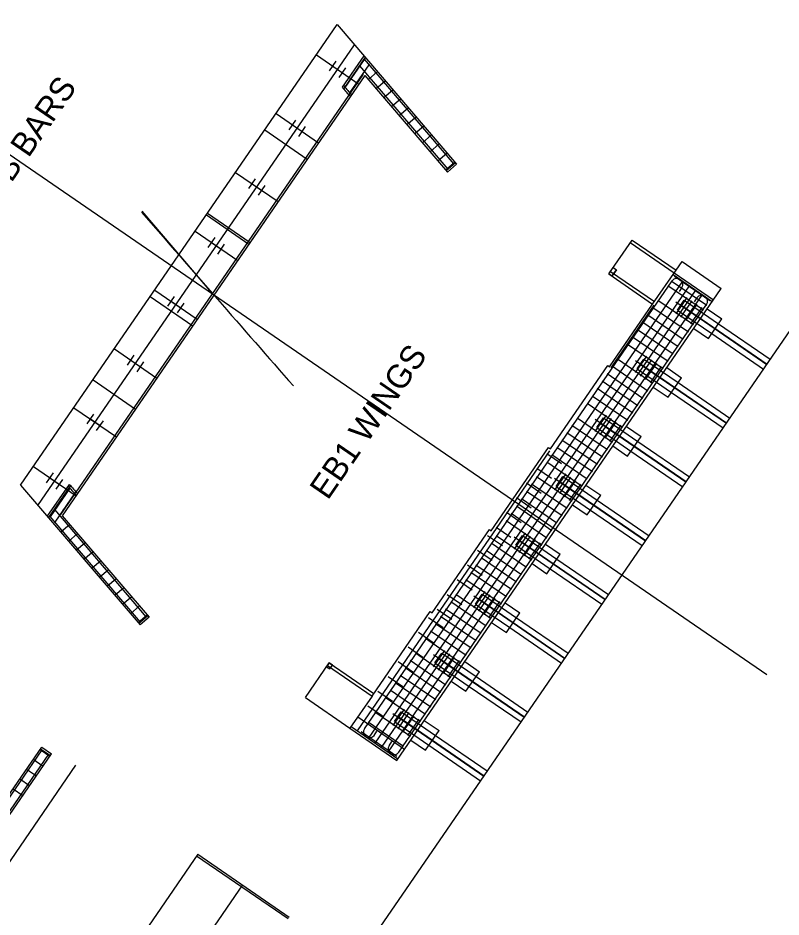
# Model space of a CAD drawing. Extents: x 2378999 to 2381348, y 331302 to 333122.
# Drawn here: x 2379189.4 to 2379253.5, y 331373.2 to 331448.8 of the extents above; entities that cross this region are included whole.
import ezdxf

# ---------------------------------------------------------------- set-up
doc = ezdxf.new("R2010")
doc.units = 0
for name, color, linetype in [('Arrowhead Terminators', 7, 'Continuous'), ('Dimension Lines', 7, 'Continuous'), ('Dimension Lines CELL', 7, 'Continuous'), ('Mis Work Point CELL', 7, 'Continuous'), ('P_SMU_Girder_Concrete', 7, 'Continuous'), ('P_SMU_Mis_Long_Chord', 7, 'Continuous'), ('P_SMU_Rebar_B_Bar', 7, 'Continuous'), ('P_SMU_Rebar_H_Bar', 7, 'Continuous'), ('P_SMU_Rebar_K_Bar', 7, 'Continuous'), ('P_SMU_Rebar_U_Bar', 7, 'Continuous'), ('P_SMU_Rebar_V_Bar', 7, 'Continuous'), ('Plan Sheet CELL', 7, 'Continuous'), ('Rebar Lines', 7, 'Continuous'), ('Scratch_Level_0', 7, 'Continuous'), ('Sup Concrete Slab Lines', 7, 'Continuous'), ('Text', 7, 'Continuous')]:
    doc.layers.add(name, color=color, linetype=linetype)

msp = doc.modelspace()

# ---------------------------------------------------------------- linework, layer by layer
at = {"layer": 'Arrowhead Terminators'}
for p, q in [((2379218.53, 331388.983), (2379244.401, 331426.64)), ((2379218.871, 331388.155), (2379245.297, 331426.619)), ((2379219.42, 331387.778), (2379245.846, 331426.241)), ((2379219.97, 331387.4), (2379246.396, 331425.864)), ((2379245.208, 331426.085), (2379244.972, 331425.742)), ((2379220.519, 331387.023), (2379246.945, 331425.486)), ((2379246.479, 331425.212), (2379246.243, 331424.869)), ((2379221.414, 331387.002), (2379247.286, 331424.658)), ((2379217.932, 331388.8), (2379234.115, 331412.355)), ((2379219.337, 331388.429), (2379219.573, 331388.772)), ((2379220.607, 331387.556), (2379220.843, 331387.899))]:
    msp.add_line(p, q, dxfattribs=at)
for centre, start, end in [((2379244.805, 331426.363), 325.50932, 145.50932), ((2379246.883, 331424.935), 325.50932, 145.50932), ((2379218.933, 331388.706), 145.50932, 325.50932), ((2379221.011, 331387.279), 145.50932, 325.50932)]:
    msp.add_arc(centre, 0.49, start, end, dxfattribs=at)
at = {"layer": 'Dimension Lines'}
for p, q in [((2379244.312, 331426.658), (2379247.3, 331424.605)), ((2379244.583, 331427.052), (2379247.571, 331424.999)), ((2379244.042, 331426.264), (2379247.03, 331424.211)), ((2379243.193, 331425.028), (2379246.18, 331422.975)), ((2379244.725, 331423.874), (2379245.669, 331425.247)), ((2379245.137, 331423.591), (2379246.081, 331424.964)), ((2379242.768, 331424.41), (2379245.756, 331422.357)), ((2379245.549, 331423.308), (2379246.493, 331424.681)), ((2379245.961, 331423.024), (2379246.905, 331424.398)), ((2379242.343, 331423.791), (2379245.331, 331421.739)), ((2379241.918, 331423.173), (2379244.906, 331421.121)), ((2379241.069, 331421.937), (2379244.057, 331419.884)), ((2379241.494, 331422.555), (2379244.482, 331420.502)), ((2379240.644, 331421.319), (2379243.632, 331419.266)), ((2379239.795, 331420.083), (2379242.783, 331418.03)), ((2379241.328, 331418.928), (2379242.271, 331420.302)), ((2379241.74, 331418.645), (2379242.683, 331420.019)), ((2379242.152, 331418.362), (2379243.096, 331419.736)), ((2379239.37, 331419.464), (2379242.358, 331417.412)), ((2379242.564, 331418.079), (2379243.508, 331419.453)), ((2379238.521, 331418.228), (2379241.509, 331416.175)), ((2379238.946, 331418.846), (2379241.933, 331416.793)), ((2379238.096, 331417.61), (2379241.084, 331415.557)), ((2379237.671, 331416.992), (2379240.659, 331414.939)), ((2379237.247, 331416.374), (2379240.235, 331414.321)), ((2379236.397, 331415.137), (2379239.385, 331413.084)), ((2379237.93, 331413.983), (2379238.874, 331415.357)), ((2379235.973, 331414.519), (2379238.96, 331412.466)), ((2379238.342, 331413.7), (2379239.286, 331415.074)), ((2379238.754, 331413.417), (2379239.698, 331414.791)), ((2379239.166, 331413.134), (2379240.11, 331414.507)), ((2379235.548, 331413.901), (2379238.536, 331411.848)), ((2379235.123, 331413.283), (2379238.111, 331411.23)), ((2379234.699, 331412.665), (2379237.686, 331410.612)), ((2379233.849, 331411.428), (2379236.837, 331409.375)), ((2379234.274, 331412.046), (2379237.262, 331409.994)), ((2379233, 331410.192), (2379235.987, 331408.139)), ((2379234.532, 331409.038), (2379235.476, 331410.412)), ((2379234.944, 331408.755), (2379235.888, 331410.128)), ((2379235.356, 331408.472), (2379236.3, 331409.845)), ((2379232.575, 331409.574), (2379235.563, 331407.521)), ((2379235.769, 331408.188), (2379236.712, 331409.562)), ((2379231.726, 331408.337), (2379234.713, 331406.285)), ((2379232.15, 331408.956), (2379235.138, 331406.903)), ((2379231.301, 331407.719), (2379234.289, 331405.667)), ((2379230.876, 331407.101), (2379233.864, 331405.048)), ((2379230.451, 331406.483), (2379233.439, 331404.43)), ((2379231.135, 331404.093), (2379232.078, 331405.466)), ((2379229.177, 331404.628), (2379232.165, 331402.576)), ((2379229.602, 331405.247), (2379232.59, 331403.194)), ((2379231.547, 331403.809), (2379232.491, 331405.183)), ((2379231.959, 331403.526), (2379232.903, 331404.9)), ((2379232.371, 331403.243), (2379233.315, 331404.617)), ((2379228.753, 331404.01), (2379231.74, 331401.958)), ((2379228.328, 331403.392), (2379231.316, 331401.339)), ((2379227.903, 331402.774), (2379230.891, 331400.721)), ((2379227.054, 331401.538), (2379230.042, 331399.485)), ((2379227.479, 331402.156), (2379230.466, 331400.103)), ((2379226.204, 331400.301), (2379229.192, 331398.249)), ((2379227.737, 331399.147), (2379228.681, 331400.521)), ((2379228.149, 331398.864), (2379229.093, 331400.238)), ((2379225.78, 331399.683), (2379228.768, 331397.63)), ((2379228.561, 331398.581), (2379229.505, 331399.955)), ((2379228.973, 331398.298), (2379229.917, 331399.672)), ((2379225.355, 331399.065), (2379228.343, 331397.012)), ((2379224.506, 331397.829), (2379227.493, 331395.776)), ((2379224.93, 331398.447), (2379227.918, 331396.394)), ((2379224.081, 331397.21), (2379227.069, 331395.158)), ((2379223.656, 331396.592), (2379226.644, 331394.54)), ((2379224.339, 331394.202), (2379225.283, 331395.576)), ((2379222.382, 331394.738), (2379225.37, 331392.685)), ((2379222.807, 331395.356), (2379225.795, 331393.303)), ((2379224.751, 331393.919), (2379225.695, 331395.292)), ((2379225.164, 331393.636), (2379226.107, 331395.009)), ((2379225.576, 331393.353), (2379226.519, 331394.726)), ((2379221.957, 331394.12), (2379224.945, 331392.067)), ((2379221.533, 331393.501), (2379224.52, 331391.449)), ((2379221.108, 331392.883), (2379224.096, 331390.831)), ((2379220.683, 331392.265), (2379223.671, 331390.212)), ((2379220.259, 331391.647), (2379223.246, 331389.594)), ((2379219.409, 331390.411), (2379222.397, 331388.358)), ((2379220.942, 331389.257), (2379221.886, 331390.63)), ((2379221.354, 331388.973), (2379222.298, 331390.347)), ((2379218.835, 331389.575), (2379221.823, 331387.523)), ((2379221.766, 331388.69), (2379222.71, 331390.064)), ((2379222.178, 331388.407), (2379223.122, 331389.781)), ((2379218.261, 331388.74), (2379221.249, 331386.687))]:
    msp.add_line(p, q, dxfattribs=at)
at = {"layer": 'Dimension Lines CELL'}
msp.add_line((2379252.362, 331393.507), (2379066.398, 331521.272), dxfattribs=at)
at = {"layer": 'Mis Work Point CELL'}
for p, q in [((2379200.252, 331343.799), (2379277.28, 331455.914)), ((2379191.082, 331407.75), (2379217.696, 331446.488))]:
    msp.add_line(p, q, dxfattribs=at)
at = {"layer": 'P_SMU_Girder_Concrete'}
for p, q in [((2379215.592, 331444.294), (2379216.159, 331445.118)), ((2379215.875, 331444.706), (2379216.686, 331444.149)), ((2379216.403, 331443.737), (2379216.969, 331444.561)), ((2379212.195, 331439.348), (2379212.761, 331440.173)), ((2379212.478, 331439.76), (2379213.288, 331439.204)), ((2379213.005, 331438.792), (2379213.571, 331439.616)), ((2379208.797, 331434.403), (2379209.363, 331435.227)), ((2379209.08, 331434.815), (2379209.891, 331434.258)), ((2379209.608, 331433.846), (2379210.174, 331434.67)), ((2379205.399, 331429.458), (2379205.966, 331430.282)), ((2379205.683, 331429.87), (2379206.493, 331429.313)), ((2379206.21, 331428.901), (2379206.776, 331429.725)), ((2379202.002, 331424.512), (2379202.568, 331425.337)), ((2379244.845, 331424.196), (2379245.412, 331425.02)), ((2379245.412, 331425.02), (2379248.296, 331423.038)), ((2379202.285, 331424.925), (2379203.095, 331424.368)), ((2379202.812, 331423.956), (2379203.379, 331424.78)), ((2379245.118, 331424.593), (2379252.348, 331419.626)), ((2379245.139, 331424.623), (2379252.369, 331419.655)), ((2379244.845, 331424.196), (2379247.73, 331422.214)), ((2379248.296, 331423.038), (2379252.642, 331420.053)), ((2379247.73, 331422.214), (2379252.075, 331419.228)), ((2379198.604, 331419.567), (2379199.17, 331420.391)), ((2379198.887, 331419.979), (2379199.698, 331419.422)), ((2379199.415, 331419.01), (2379199.981, 331419.834)), ((2379241.448, 331419.25), (2379242.014, 331420.075)), ((2379241.741, 331419.677), (2379248.971, 331414.71)), ((2379242.014, 331420.075), (2379244.899, 331418.093)), ((2379241.448, 331419.25), (2379244.332, 331417.268)), ((2379241.72, 331419.648), (2379248.951, 331414.68)), ((2379244.899, 331418.093), (2379249.244, 331415.107)), ((2379244.332, 331417.268), (2379248.678, 331414.283)), ((2379195.207, 331414.622), (2379195.773, 331415.446)), ((2379238.05, 331414.305), (2379238.616, 331415.129)), ((2379238.616, 331415.129), (2379241.501, 331413.147)), ((2379195.49, 331415.034), (2379196.3, 331414.477)), ((2379196.017, 331414.065), (2379196.583, 331414.889)), ((2379238.323, 331414.702), (2379245.553, 331409.735)), ((2379238.343, 331414.732), (2379245.573, 331409.765)), ((2379238.05, 331414.305), (2379240.935, 331412.323)), ((2379241.501, 331413.147), (2379245.846, 331410.162)), ((2379240.935, 331412.323), (2379245.28, 331409.338)), ((2379191.809, 331409.676), (2379192.375, 331410.501)), ((2379192.092, 331410.089), (2379192.903, 331409.532)), ((2379192.619, 331409.12), (2379193.186, 331409.944)), ((2379234.652, 331409.36), (2379235.219, 331410.184)), ((2379235.219, 331410.184), (2379238.103, 331408.202)), ((2379234.652, 331409.36), (2379237.537, 331407.378)), ((2379234.925, 331409.757), (2379242.155, 331404.79)), ((2379234.946, 331409.787), (2379242.176, 331404.819)), ((2379238.103, 331408.202), (2379242.449, 331405.217)), ((2379237.537, 331407.378), (2379241.882, 331404.392)), ((2379231.255, 331404.414), (2379231.821, 331405.239)), ((2379231.528, 331404.812), (2379238.758, 331399.844)), ((2379231.548, 331404.842), (2379238.778, 331399.874)), ((2379231.821, 331405.239), (2379234.706, 331403.257)), ((2379231.255, 331404.414), (2379234.139, 331402.433)), ((2379234.706, 331403.257), (2379239.051, 331400.271)), ((2379234.139, 331402.433), (2379238.485, 331399.447)), ((2379227.857, 331399.469), (2379228.423, 331400.293)), ((2379228.423, 331400.293), (2379231.308, 331398.311)), ((2379227.857, 331399.469), (2379230.742, 331397.487)), ((2379228.13, 331399.866), (2379235.36, 331394.899)), ((2379228.15, 331399.896), (2379235.381, 331394.929)), ((2379231.308, 331398.311), (2379235.653, 331395.326)), ((2379230.742, 331397.487), (2379235.087, 331394.502)), ((2379224.459, 331394.524), (2379225.026, 331395.348)), ((2379224.732, 331394.921), (2379231.962, 331389.954)), ((2379224.753, 331394.951), (2379231.983, 331389.984)), ((2379225.026, 331395.348), (2379227.91, 331393.366)), ((2379224.459, 331394.524), (2379227.344, 331392.542)), ((2379227.91, 331393.366), (2379232.256, 331390.381)), ((2379227.344, 331392.542), (2379231.689, 331389.557)), ((2379221.062, 331389.579), (2379221.628, 331390.403)), ((2379221.628, 331390.403), (2379224.513, 331388.421)), ((2379221.062, 331389.579), (2379223.947, 331387.597)), ((2379221.335, 331389.976), (2379228.565, 331385.008)), ((2379221.355, 331390.006), (2379228.585, 331385.038)), ((2379224.513, 331388.421), (2379228.858, 331385.435)), ((2379223.947, 331387.597), (2379228.292, 331384.611))]:
    msp.add_line(p, q, dxfattribs=at)
at = {"layer": 'P_SMU_Mis_Long_Chord'}
msp.add_arc((2384538.133, 336083.063), 7080, 221.0615597, 221.2186539, dxfattribs=at)
at = {"layer": 'P_SMU_Rebar_B_Bar'}
for p, q in [((2379189.625, 331409.455), (2379216.239, 331448.193)), ((2379216.239, 331448.193), (2379226.276, 331436.446)), ((2379218.481, 331445.57), (2379216.665, 331442.926)), ((2379218.567, 331443.929), (2379193.125, 331406.897)), ((2379218.567, 331443.929), (2379225.516, 331435.796)), ((2379210.152, 331439.333), (2379213.724, 331436.879)), ((2379225.516, 331435.796), (2379226.276, 331436.446)), ((2379205.339, 331432.327), (2379208.91, 331429.873)), ((2379239.063, 331427.226), (2379241.024, 331430.081)), ((2379240.873, 331429.86), (2379244.567, 331427.322)), ((2379241.024, 331430.081), (2379244.719, 331427.543)), ((2379244.719, 331427.543), (2379245.224, 331428.279)), ((2379245.224, 331428.279), (2379248.521, 331426.014)), ((2379239.063, 331427.226), (2379242.757, 331424.688)), ((2379239.209, 331427.438), (2379242.903, 331424.9)), ((2379239.338, 331427.038), (2379239.703, 331427.569)), ((2379239.428, 331427.757), (2379239.703, 331427.569)), ((2379242.757, 331424.688), (2379244.719, 331427.543)), ((2379244.567, 331427.322), (2379247.864, 331425.057)), ((2379221.249, 331386.319), (2379248.521, 331426.014)), ((2379200.525, 331425.321), (2379204.097, 331422.867)), ((2379239.137, 331419.419), (2379242.757, 331424.688)), ((2379247.343, 331424.299), (2379248.579, 331423.45)), ((2379247.447, 331421.802), (2379248.579, 331423.45)), ((2379246.211, 331422.651), (2379247.447, 331421.802)), ((2379234.163, 331412.524), (2379238.976, 331419.529)), ((2379238.976, 331419.529), (2379239.137, 331419.419)), ((2379243.945, 331419.354), (2379245.182, 331418.505)), ((2379195.712, 331418.315), (2379199.284, 331415.862)), ((2379244.049, 331416.856), (2379245.182, 331418.505)), ((2379242.813, 331417.706), (2379244.049, 331416.856)), ((2379240.548, 331414.409), (2379241.784, 331413.559)), ((2379240.652, 331411.911), (2379241.784, 331413.559)), ((2379229.19, 331405.628), (2379234.003, 331412.633)), ((2379234.003, 331412.633), (2379234.163, 331412.524)), ((2379239.415, 331412.76), (2379240.652, 331411.911)), ((2379189.625, 331409.455), (2379199.661, 331397.708)), ((2379191.866, 331406.831), (2379193.72, 331409.529)), ((2379237.15, 331409.464), (2379238.387, 331408.614)), ((2379237.254, 331406.966), (2379238.387, 331408.614)), ((2379236.018, 331407.815), (2379237.254, 331406.966)), ((2379193.125, 331406.897), (2379200.421, 331398.357)), ((2379224.216, 331398.732), (2379229.029, 331405.738)), ((2379229.029, 331405.738), (2379229.19, 331405.628)), ((2379233.753, 331404.518), (2379234.989, 331403.669)), ((2379233.856, 331402.02), (2379234.989, 331403.669)), ((2379232.62, 331402.87), (2379233.856, 331402.02)), ((2379230.355, 331399.573), (2379231.591, 331398.724)), ((2379219.172, 331391.733), (2379224.056, 331398.842)), ((2379224.056, 331398.842), (2379224.216, 331398.732)), ((2379230.459, 331397.075), (2379231.591, 331398.724)), ((2379200.421, 331398.357), (2379199.661, 331397.708)), ((2379229.222, 331397.925), (2379230.459, 331397.075)), ((2379213.561, 331391.601), (2379215.567, 331394.52)), ((2379215.348, 331394.201), (2379215.622, 331394.012)), ((2379215.422, 331394.309), (2379219.172, 331391.733)), ((2379215.567, 331394.52), (2379219.316, 331391.944)), ((2379215.622, 331394.012), (2379215.842, 331394.331)), ((2379226.957, 331394.628), (2379228.194, 331393.778)), ((2379227.061, 331392.13), (2379228.194, 331393.778)), ((2379225.825, 331392.979), (2379227.061, 331392.13)), ((2379219.172, 331391.733), (2379217.311, 331389.025)), ((2379213.561, 331391.601), (2379217.311, 331389.025)), ((2379217.968, 331389.982), (2379221.906, 331387.276)), ((2379223.56, 331389.682), (2379224.796, 331388.833)), ((2379217.311, 331389.025), (2379221.249, 331386.319)), ((2379223.663, 331387.184), (2379224.796, 331388.833)), ((2379222.427, 331388.034), (2379223.663, 331387.184)), ((2379185.037, 331378.187), (2379191.397, 331387.446)), ((2379191.397, 331387.446), (2379192.222, 331386.879)), ((2379183.472, 331374.144), (2379192.222, 331386.879)), ((2379204.515, 331378.433), (2379197.24, 331367.844)), ((2379204.515, 331378.433), (2379212.202, 331373.152)), ((2379208.264, 331375.857), (2379201.469, 331365.967))]:
    msp.add_line(p, q, dxfattribs=at)
for points in [[(2379239.428, 331427.757), (2379239.703, 331427.569), (2379239.338, 331427.038), (2379239.063, 331427.226)], [(2379215.567, 331394.52), (2379215.348, 331394.201), (2379215.622, 331394.012), (2379215.842, 331394.331)]]:
    msp.add_lwpolyline(points, close=True, dxfattribs=at)
for radius, start, end in [(7060.375, 221.0873052, 221.0956842), (7099.625, 221.1687496, 221.1770793)]:
    msp.add_arc((2384538.133, 336083.063), radius, start, end, dxfattribs=at)
at = {"layer": 'P_SMU_Rebar_H_Bar'}
for p, q in [((2379218.105, 331444.727), (2379217.633, 331444.04)), ((2379218.495, 331445.296), (2379218.023, 331444.609)), ((2379218.105, 331444.727), (2379225.534, 331436.031)), ((2379218.495, 331445.296), (2379226.041, 331436.464)), ((2379192.467, 331407.411), (2379192.939, 331408.098)), ((2379192.076, 331406.842), (2379192.548, 331407.529)), ((2379192.076, 331406.842), (2379199.68, 331397.943)), ((2379192.467, 331407.411), (2379200.186, 331398.376)), ((2379184.711, 331377.419), (2379191.44, 331387.214)), ((2379185.361, 331377.189), (2379191.99, 331386.836)), ((2379187.546, 331376.117), (2379194.276, 331385.912))]:
    msp.add_line(p, q, dxfattribs=at)
at = {"layer": 'P_SMU_Rebar_K_Bar'}
for p, q in [((2379216.904, 331442.906), (2379218.523, 331445.263)), ((2379217.308, 331442.465), (2379218.916, 331444.804)), ((2379193.764, 331409.226), (2379192.104, 331406.81)), ((2379194.16, 331408.773), (2379192.496, 331406.35))]:
    msp.add_line(p, q, dxfattribs=at)
at = {"layer": 'P_SMU_Rebar_U_Bar'}
for p, q in [((2379233.857, 331412.127), (2379235.094, 331411.278)), ((2379233.008, 331410.891), (2379234.244, 331410.041)), ((2379232.158, 331409.654), (2379233.395, 331408.805)), ((2379231.309, 331408.418), (2379232.545, 331407.569)), ((2379230.46, 331407.182), (2379231.696, 331406.332)), ((2379229.61, 331405.945), (2379230.847, 331405.096)), ((2379228.883, 331405.232), (2379230.12, 331404.382)), ((2379228.034, 331403.995), (2379229.27, 331403.146)), ((2379227.184, 331402.759), (2379228.421, 331401.91)), ((2379226.335, 331401.523), (2379227.571, 331400.673)), ((2379225.486, 331400.286), (2379226.722, 331399.437)), ((2379224.636, 331399.05), (2379225.872, 331398.201)), ((2379223.91, 331398.336), (2379225.146, 331397.486)), ((2379223.061, 331397.099), (2379224.297, 331396.25)), ((2379222.211, 331395.863), (2379223.447, 331395.014)), ((2379221.362, 331394.627), (2379222.598, 331393.777)), ((2379220.512, 331393.39), (2379221.749, 331392.541)), ((2379219.663, 331392.154), (2379220.899, 331391.305)), ((2379218.814, 331390.918), (2379220.05, 331390.068))]:
    msp.add_line(p, q, dxfattribs=at)
at = {"layer": 'P_SMU_Rebar_V_Bar'}
for centre in [(2379218.132, 331444.731), (2379218.497, 331445.262), (2379218.917, 331444.77), (2379217.845, 331444.313), (2379218.552, 331444.238), (2379219.475, 331444.117), (2379217.373, 331443.626), (2379217.798, 331443.14), (2379218.269, 331443.827), (2379219, 331443.711), (2379220.125, 331443.357), (2379216.902, 331442.94), (2379217.326, 331442.453), (2379219.65, 331442.951), (2379220.774, 331442.597), (2379220.299, 331442.191), (2379221.424, 331441.836), (2379220.949, 331441.43), (2379222.073, 331441.076), (2379221.598, 331440.67), (2379222.723, 331440.316), (2379222.248, 331439.91), (2379223.373, 331439.555), (2379222.897, 331439.149), (2379224.022, 331438.795), (2379223.547, 331438.389), (2379224.672, 331438.035), (2379224.197, 331437.629), (2379225.321, 331437.275), (2379224.846, 331436.869), (2379225.971, 331436.514), (2379225.496, 331436.108), (2379193.738, 331409.225), (2379193.266, 331408.538), (2379194.163, 331408.739), (2379192.794, 331407.851), (2379193.691, 331408.052), (2379192.102, 331406.844), (2379192.468, 331407.377), (2379192.889, 331406.885), (2379193.219, 331407.365), (2379192.523, 331406.352), (2379193.145, 331405.623), (2379193.621, 331406.029), (2379193.795, 331404.862), (2379194.27, 331405.268), (2379194.445, 331404.102), (2379194.92, 331404.508), (2379195.094, 331403.342), (2379195.569, 331403.748), (2379195.744, 331402.581), (2379196.219, 331402.987), (2379196.393, 331401.821), (2379196.869, 331402.227), (2379197.043, 331401.061), (2379197.518, 331401.467), (2379197.692, 331400.3), (2379198.168, 331400.706), (2379198.342, 331399.54), (2379198.817, 331399.946), (2379198.992, 331398.78), (2379199.467, 331399.186), (2379199.641, 331398.02), (2379200.116, 331398.426), (2379191.41, 331387.133), (2379191.925, 331386.779), (2379190.844, 331386.309), (2379191.359, 331385.955), (2379190.278, 331385.485), (2379190.793, 331385.131), (2379189.711, 331384.661), (2379190.227, 331384.307), (2379189.66, 331383.483)]:
    msp.add_circle(centre, 0.0208, dxfattribs=at)
at = {"layer": 'Plan Sheet CELL'}
msp.add_line((2379205.87, 331425.449), (2379199.839, 331432.508), dxfattribs=at)
at = {"layer": 'Rebar Lines'}
for p, q in [((2379214.495, 331445.654), (2379218.067, 331443.2)), ((2379211.097, 331440.709), (2379214.669, 331438.255)), ((2379207.7, 331435.764), (2379211.271, 331433.31)), ((2379204.302, 331430.818), (2379207.874, 331428.364)), ((2379200.904, 331425.873), (2379204.476, 331423.419)), ((2379244.709, 331424.896), (2379252.358, 331419.64)), ((2379197.507, 331420.928), (2379201.078, 331418.474)), ((2379241.311, 331419.951), (2379248.961, 331414.695)), ((2379194.109, 331415.982), (2379197.681, 331413.529)), ((2379237.914, 331415.005), (2379245.563, 331409.75)), ((2379190.711, 331411.037), (2379194.283, 331408.583)), ((2379234.516, 331410.06), (2379242.166, 331404.805)), ((2379231.118, 331405.115), (2379238.768, 331399.859)), ((2379227.721, 331400.169), (2379235.37, 331394.914)), ((2379224.323, 331395.224), (2379231.973, 331389.969)), ((2379220.926, 331390.279), (2379228.575, 331385.023))]:
    msp.add_line(p, q, dxfattribs=at)
at = {"layer": 'Scratch_Level_0'}
for p, q in [((2379218.618, 331445.475), (2379216.802, 331442.832)), ((2379218.43, 331444.024), (2379192.988, 331406.992)), ((2379218.857, 331443.589), (2379219.618, 331444.239)), ((2379219.507, 331442.829), (2379220.267, 331443.479)), ((2379220.157, 331442.069), (2379220.917, 331442.718)), ((2379220.806, 331441.309), (2379221.566, 331441.958)), ((2379221.456, 331440.548), (2379222.216, 331441.198)), ((2379222.105, 331439.788), (2379222.866, 331440.438)), ((2379222.755, 331439.028), (2379223.515, 331439.677)), ((2379223.404, 331438.267), (2379224.165, 331438.917)), ((2379224.054, 331437.507), (2379224.814, 331438.157)), ((2379224.704, 331436.747), (2379225.464, 331437.396)), ((2379225.353, 331435.986), (2379226.113, 331436.636)), ((2379225.407, 331435.923), (2379226.168, 331436.573)), ((2379205.244, 331432.19), (2379208.816, 331429.736)), ((2379244.472, 331427.185), (2379247.769, 331424.92)), ((2379239.274, 331419.325), (2379242.894, 331424.594)), ((2379192.004, 331406.737), (2379193.857, 331409.435)), ((2379193.763, 331406.15), (2379193.003, 331405.501)), ((2379194.413, 331405.39), (2379193.653, 331404.74)), ((2379195.062, 331404.63), (2379194.302, 331403.98)), ((2379195.712, 331403.869), (2379194.952, 331403.22)), ((2379196.362, 331403.109), (2379195.601, 331402.46)), ((2379197.011, 331402.349), (2379196.251, 331401.699)), ((2379197.661, 331401.589), (2379196.9, 331400.939)), ((2379198.31, 331400.828), (2379197.55, 331400.179)), ((2379198.96, 331400.068), (2379198.2, 331399.418)), ((2379199.609, 331399.308), (2379198.849, 331398.658)), ((2379200.259, 331398.547), (2379199.499, 331397.898)), ((2379200.313, 331398.484), (2379199.553, 331397.834)), ((2379217.405, 331389.162), (2379221.343, 331386.456)), ((2379191.256, 331387.24), (2379192.08, 331386.673)), ((2379191.303, 331387.308), (2379192.127, 331386.742)), ((2379190.689, 331386.415), (2379191.514, 331385.849)), ((2379190.123, 331385.591), (2379190.947, 331385.025)), ((2379189.557, 331384.767), (2379190.381, 331384.201)), ((2379188.991, 331383.943), (2379189.815, 331383.376)), ((2379204.421, 331378.296), (2379212.108, 331373.014))]:
    msp.add_line(p, q, dxfattribs=at)
for radius, start, end in [(7060.208, 221.0873052, 221.0956842), (7099.792, 221.1687496, 221.1770793)]:
    msp.add_arc((2384538.133, 336083.063), radius, start, end, dxfattribs=at)
at = {"layer": 'Text'}
msp.add_line((2379204.399, 331427.134), (2379204.399, 331427.134), dxfattribs=at)

# ---------------------------------------------------------------- texts
at = {"layer": 'Sup Concrete Slab Lines'}
for s, p in [('EB1 TOP B BARS', (2379182.033, 331424.926)), ('EB1 WINGS', (2379215.448, 331408.14))]:
    msp.add_text(s, height=2, rotation=55.50932, dxfattribs=at).set_placement(p)

doc.saveas('drawing.dxf')
